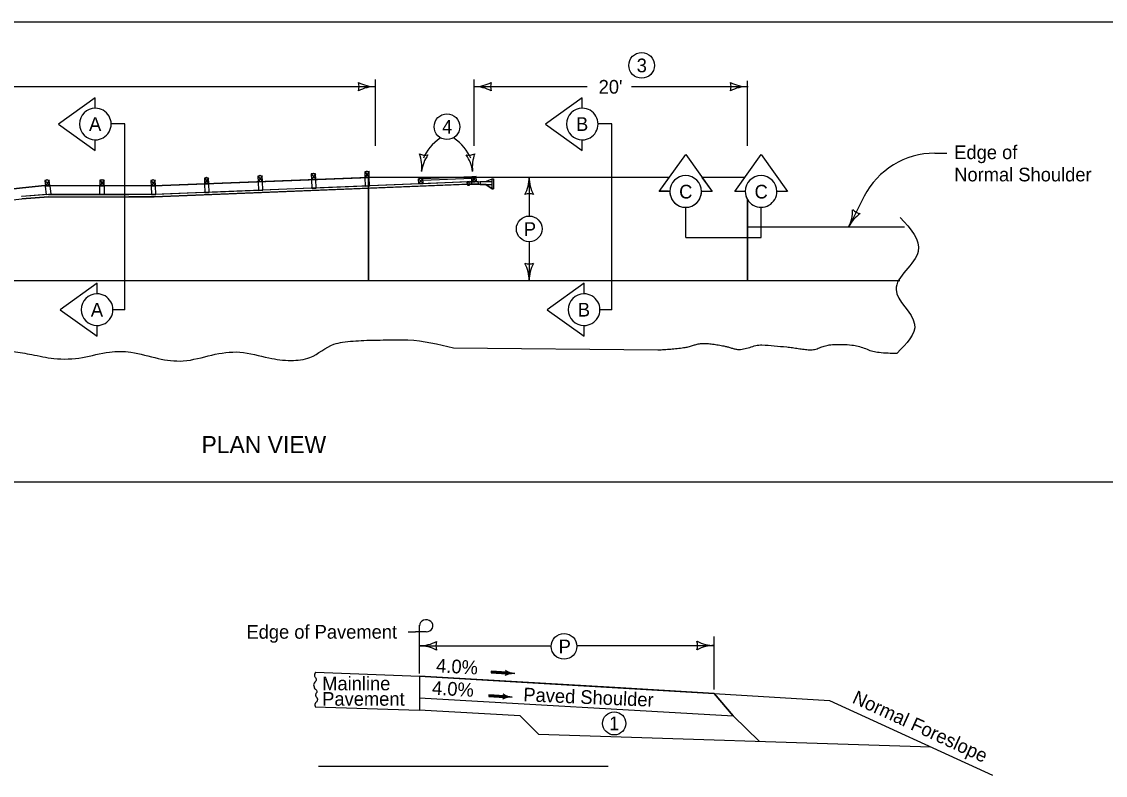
# Model space of a CAD drawing. Extents: x -1548 to 1548, y -960 to 993.
# Drawn here: x -756 to 510, y -231 to 650 of the extents above; entities that cross this region are included whole.
import ezdxf

# ---------------------------------------------------------------- set-up
doc = ezdxf.new("R2010")
doc.units = 0
for name, color, linetype in [('dsnCellElements', 7, 'Continuous'), ('dsnStdBorder', 7, 'Continuous'), ('dsnStdDimension', 7, 'Continuous'), ('dsnStdLabel', 7, 'Continuous'), ('dsnStdLineWork', 7, 'Continuous'), ('dsnStdNote', 7, 'Continuous'), ('dsnStdSection', 7, 'Continuous'), ('dsnStdShading', 7, 'Continuous'), ('Level 4', 7, 'Continuous')]:
    doc.layers.add(name, color=color, linetype=linetype)

msp = doc.modelspace()

# ---------------------------------------------------------------- linework, layer by layer
at = {"layer": 'dsnCellElements'}
for p, q in [((-480.2, 469.6), (-474.9, 463.1)), ((-475.2, 469.8), (-479.9, 462.9)), ((-478.1, 469.7), (-478.2, 469.8)), ((-477.7, 470.7), (-477.7, 470.7)), ((-417.8, 472.1), (-412.5, 465.6)), ((-412.8, 472.3), (-417.5, 465.4)), ((-415.3, 473.2), (-415.3, 473.2)), ((-355.3, 474.6), (-350, 468.1)), ((-350.3, 474.8), (-355, 467.9)), ((-352.8, 475.6), (-352.8, 475.7)), ((-230.2, 468.8), (-287.3, 466.5)), ((-728.9, 464.4), (-723.2, 458.3)), ((-723.9, 464.9), (-728.2, 457.8)), ((-728.2, 457.8), (-723.2, 458.3)), ((-725.7, 458), (-728.2, 457.8)), ((-725.7, 458), (-728.2, 457.8)), ((-727.2, 447.8), (-728.2, 457.8)), ((-726.5, 465.6), (-726.5, 465.7)), ((-723.2, 458.3), (-722.2, 448.3)), ((-664.7, 464.7), (-659.7, 458.1)), ((-659.7, 464.7), (-664.7, 458.1)), ((-664.7, 458.1), (-659.7, 458.1)), ((-664.7, 448.1), (-664.7, 458.1)), ((-662.2, 465.7), (-662.2, 465.8)), ((-659.7, 458.1), (-659.7, 448.1)), ((-605.1, 464.6), (-599.8, 458.1)), ((-600.1, 464.8), (-604.8, 457.9)), ((-602.6, 465.7), (-602.6, 465.7)), ((-222.6, 463.2), (-601.6, 448.1)), ((-222.5, 460.5), (-601.5, 445.3)), ((-601.5, 445.3), (-235.4, 460)), ((-542.7, 467.1), (-537.4, 460.6)), ((-537.7, 467.3), (-542.4, 460.4)), ((-540.2, 468.2), (-540.2, 468.2)), ((-350.2, 458.1), (-354.6, 457.9)), ((-288.4, 460.6), (-292.1, 460.4)), ((-288.4, 460.6), (-292.1, 460.4)), ((-235.4, 460), (-235.6, 462.7)), ((-233, 462.6), (-220.4, 463.2)), ((-220.3, 460), (-232.9, 459.5)), ((-230.1, 459.6), (-230.2, 462.8)), ((-222.5, 460.5), (-222.6, 463.2)), ((-727.2, 447.9), (-756.2, 445.6)), ((-724.8, 448), (-756.1, 445.6)), ((-755.9, 442.9), (-724.6, 445.3)), ((-724.6, 445.3), (-755.9, 442.9)), ((-722.2, 448.3), (-727.2, 447.8)), ((-724.7, 448.1), (-727.2, 447.8)), ((-727.2, 447.8), (-727.2, 447.9)), ((-664.7, 448.1), (-724.7, 448.1)), ((-724.7, 448.1), (-631, 448.1)), ((-724.6, 445.3), (-631, 445.3)), ((-724.6, 445.3), (-631, 445.3)), ((-659.7, 448.1), (-664.7, 448.1)), ((-659.7, 448.1), (-664.7, 448.1)), ((-631, 448.1), (-659.7, 448.1)), ((-604.4, 448.1), (-631, 448.1)), ((-601.6, 448.1), (-631, 448.1)), ((-631, 445.3), (-601.5, 445.3)), ((-601.5, 445.3), (-631, 445.3)), ((-474.5, 453.1), (-479.5, 452.9)), ((-880.3, 430.4), (-755.9, 442.9)), ((-880.3, 430.4), (-755.9, 442.9))]:
    msp.add_line(p, q, dxfattribs=at)
for points in [[(-479.9, 462.9), (-474.9, 463.1), (-475.2, 469.8), (-480.2, 469.6)], [(-417.5, 465.4), (-412.5, 465.6), (-412.8, 472.3), (-417.8, 472.1)], [(-355, 467.9), (-350, 468.1), (-350.3, 474.8), (-355.3, 474.6)], [(-728.2, 457.8), (-723.2, 458.3), (-723.9, 464.9), (-728.9, 464.4)], [(-664.7, 458.1), (-659.7, 458.1), (-659.7, 464.7), (-664.7, 464.7)], [(-604.8, 457.9), (-599.8, 458.1), (-600.1, 464.8), (-605.1, 464.6)], [(-604.4, 447.9), (-599.4, 448.1), (-599.8, 458.1), (-604.8, 457.9)], [(-542.4, 460.4), (-537.4, 460.6), (-537.7, 467.3), (-542.7, 467.1)], [(-542, 450.4), (-537, 450.6), (-537.4, 460.6), (-542.4, 460.4)], [(-479.5, 452.9), (-474.5, 453.1), (-474.9, 463.1), (-479.9, 462.9)], [(-417.1, 455.4), (-412.1, 455.6), (-412.5, 465.6), (-417.5, 465.4)], [(-354.6, 457.9), (-349.6, 458.1), (-350, 468.1), (-355, 467.9)], [(-235.6, 462.7), (-220.4, 463.3), (-214, 463.2), (-206.4, 466.5), (-204.7, 466.5), (-204.9, 454.8), (-206.5, 454.8), (-213.9, 459.8), (-220.3, 459.8), (-232.9, 459.3), (-235.4, 459.2)], [(-233.1, 462.8), (-233.1, 463.1), (-235.6, 463), (-235.6, 462.7), (-235.4, 459.2), (-235.4, 458.9), (-232.9, 459), (-232.9, 459.3)]]:
    msp.add_lwpolyline(points, close=True, dxfattribs=at)
for points in [[(-478, 469.7), (-478.1, 470.1), (-477.4, 470.1), (-477.4, 469.7)], [(-477.9, 470.1), (-477.9, 470.7), (-477.6, 470.7), (-477.5, 470.1)], [(-415.6, 472.2), (-415.6, 472.6), (-414.9, 472.6), (-414.9, 472.2)], [(-415.5, 472.6), (-415.5, 473.1), (-415.1, 473.2), (-415.1, 472.6)], [(-353.1, 474.7), (-353.2, 475.1), (-352.5, 475.1), (-352.5, 474.7)], [(-353, 475.1), (-353, 475.6), (-352.7, 475.7), (-352.6, 475.1)], [(-230.2, 468.8), (-287.3, 466.5)], [(-230.1, 466.6), (-230.2, 468.8)], [(-230, 469), (-225.9, 469.2)], [(-225, 469.1), (-230, 468.9)], [(-230, 468.9), (-225.9, 469)], [(-229.8, 462.9), (-230, 469)], [(-224.7, 463.3), (-230, 468.9)], [(-229.9, 466.6), (-230, 468.8)], [(-229.8, 463.1), (-225, 469.1)], [(-225.9, 469.2), (-225.9, 469)], [(-224.7, 463.3), (-225, 469.1)], [(-726.7, 464.6), (-726.8, 465), (-726.1, 465.1), (-726.1, 464.7)], [(-726.6, 465.1), (-726.7, 465.6), (-726.3, 465.6), (-726.2, 465.1)], [(-662.6, 464.7), (-662.6, 465.2), (-661.9, 465.2), (-661.9, 464.7)], [(-662.4, 465.2), (-662.4, 465.7), (-662, 465.7), (-662, 465.2)], [(-602.9, 464.7), (-603, 465.1), (-602.3, 465.1), (-602.3, 464.7)], [(-602.8, 465.1), (-602.8, 465.7), (-602.5, 465.7), (-602.4, 465.1)], [(-540.5, 467.2), (-540.5, 467.6), (-539.8, 467.6), (-539.8, 467.2)], [(-540.4, 467.6), (-540.4, 468.2), (-540, 468.2), (-540, 467.6)], [(-354.6, 457.9), (-355.2, 457.9), (-412.1, 455.6)], [(-350.2, 458.1), (-355.2, 457.9)], [(-292.1, 460.4), (-349.6, 458.1), (-350.2, 458.1)], [(-287.5, 466.7), (-292.4, 466.5)], [(-287.4, 466.6), (-292.4, 466.4)], [(-292.2, 460.4), (-292.4, 466.5)], [(-287.2, 460.8), (-292.4, 466.4)], [(-292.2, 460.6), (-287.4, 466.6)], [(-287.2, 460.8), (-292.2, 460.6)], [(-287.2, 460.6), (-292.2, 460.4)], [(-235.6, 462.7), (-287.2, 460.6), (-288.4, 460.6)], [(-287.2, 461.2), (-287.4, 466.6)], [(-287.1, 461.2), (-287.3, 466.5)], [(-230.1, 466.8), (-287.2, 464.5)], [(-230.1, 466.7), (-287.2, 464.5)], [(-287.2, 460.8), (-287.2, 461.2)], [(-287, 460.8), (-287.1, 461.2)], [(-232.9, 459.3), (-235.4, 459.2), (-235.6, 462.7), (-233.1, 462.8)], [(-233.1, 462.8), (-220.4, 463.3), (-220.3, 459.8), (-232.9, 459.3)], [(-230, 463.7), (-230.1, 466.6)], [(-230, 463.5), (-230, 463.7)], [(-230, 463.1), (-230, 463.5)], [(-229.8, 463.7), (-229.9, 466.6)], [(-229.8, 463.5), (-229.8, 463.7)], [(-229.8, 463.1), (-229.8, 463.5)], [(-224.7, 463.3), (-229.8, 463.1)], [(-229.8, 463.1), (-225.7, 463.2)], [(-229.8, 462.9), (-225.7, 463.1)], [(-225.9, 463), (-229.4, 462.9)], [(-220.4, 463.3), (-206.4, 463.1)], [(-220.3, 459.8), (-206.5, 459.7)], [(-214, 463.2), (-206.4, 466.5)], [(-213.9, 459.8), (-206.5, 454.8)], [(-206.5, 454.8), (-206.4, 466.5)], [(-206.4, 466.5), (-204.7, 466.5)], [(-204.9, 454.9), (-206.4, 455), (-206.3, 466.4), (-204.7, 466.4)], [(-204.7, 466.5), (-204.9, 454.8)], [(-599.4, 448.1), (-599.4, 448.1), (-601.6, 448.1), (-604.4, 447.9), (-604.4, 448.1)], [(-479.5, 452.9), (-537, 450.6), (-537.7, 450.6), (-542, 450.4), (-542.7, 450.4), (-599.4, 448.1)], [(-537.7, 450.6), (-542.7, 450.4)], [(-417.1, 455.4), (-417.7, 455.4), (-474.5, 453.1)], [(-412.7, 455.6), (-417.7, 455.4)], [(-412.1, 455.6), (-412.7, 455.6), (-417.1, 455.4)], [(-206.5, 454.8), (-204.9, 454.8)]]:
    msp.add_lwpolyline(points, dxfattribs=at)
for centre, radius, start, end in [((-230, 468.8), 0.208, 92.2853, 182.2853), ((-230, 468.8), 0.0517, 92.2853, 182.2853), ((-287.5, 466.5), 0.208, 2.2853, 92.2853), ((-287.2, 460.8), 0.208, 272.2853, 2.2853), ((-229.8, 463.1), 0.208, 182.2853, 272.2853), ((-229.8, 463.1), 0.0517, 182.2853, 272.2853)]:
    msp.add_arc(centre, radius, start, end, dxfattribs=at)
at = {"layer": 'dsnStdBorder'}
msp.add_line((-1547.8, 650), (1547.8, 650), dxfattribs=at)
at = {"layer": 'dsnStdDimension'}
for p, q in [((-1247.4, 574.1), (-342.6, 574.1)), ((-342.6, 504.9), (-342.6, 582.3)), ((-227.5, 504.9), (-227.5, 582.3)), ((-227.5, 574.1), (-95.3, 574.1)), ((-43.7, 574.1), (92.7, 574.1)), ((92, 504.9), (92, 581)), ((-163.1, 468.1), (-163.1, 422.9)), ((-163.1, 392.9), (-163.1, 347.6)), ((53, -130.2), (53, -68.5)), ((-291.3, -79.1), (-137.4, -79.1)), ((-107.5, -78.9), (53, -78.9))]:
    msp.add_line(p, q, dxfattribs=at)
for centre in [(-163.1, 407.9), (-122.4, -79.9)]:
    msp.add_circle(centre, 15, dxfattribs=at)
for centre, radius, start, end in [((-378.2, 574.1), 16.4, 342.2666, 17.7333), ((-342.6, 616.6), 42.5, 241.9275, 270), ((-342.6, 531.6), 42.5, 90, 118.0725), ((-227.5, 616.6), 42.5, 270, 298.0725), ((-227.5, 531.6), 42.5, 61.9275, 90), ((-191.8, 574.1), 16.4, 162.2666, 197.7334), ((56.3, 574.1), 16.4, 342.2666, 17.7333), ((92, 616.6), 42.5, 241.9275, 270), ((92, 531.6), 42.5, 90, 118.0725), ((-205.6, 468.1), 42.5, 331.9275, 0), ((-120.6, 468.1), 42.5, 180, 208.0725), ((-163.1, 432.5), 16.4, 72.2666, 107.7334), ((-163.1, 383.3), 16.4, 252.2666, 287.7333), ((-205.6, 347.6), 42.5, 360, 28.0725), ((-120.6, 347.6), 42.5, 151.9275, 180), ((-291.3, -36.6), 42.5, 270, 298.0725), ((-255.7, -79.1), 16.4, 162.2666, 197.7334), ((17.3, -78.9), 16.4, 342.2666, 17.7333), ((53, -36.4), 42.5, 241.9275, 270), ((-291.3, -121.6), 42.5, 61.9275, 90), ((53, -121.4), 42.5, 90, 118.0725)]:
    msp.add_arc(centre, radius, start, end, dxfattribs=at)
at = {"layer": 'dsnStdLabel'}
for p, q in [((310.7, 496.3), (325, 496.3)), ((228.4, 446), (210.2, 410.3)), ((-304.7, -62.9), (-296, -62.9)), ((-283.5, -62.9), (-296, -62.9)), ((-291.3, -75.7), (-291.3, -54.9)), ((-291.3, -111.7), (-291.3, -75.7)), ((-189.4, -110.9), (-207.6, -109.9)), ((-189.5, -111.8), (-189.5, -111.8)), ((-189.3, -109.9), (-189.3, -109.9)), ((-192.2, -138.5), (-210.4, -137.5)), ((-192.2, -137.5), (-192.2, -137.5)), ((-192.3, -139.5), (-192.3, -139.5))]:
    msp.add_line(p, q, dxfattribs=at)
for points in [[(-189.3, -110), (-207.5, -108.9), (-207.6, -110.8), (-189.5, -111.8), (-189.4, -110.2), (-207.3, -109.1), (-207.3, -110.6), (-189.8, -111.6), (-189.7, -110.5), (-207, -109.4), (-207.1, -110.4), (-190.1, -111.4), (-190, -110.7), (-206.8, -109.6), (-206.9, -110.2), (-190.3, -111.1)], [(-189.7, -108.7), (-189, -109.9), (-189.1, -111.5), (-189.8, -112.9), (-187.1, -112.1), (-183.9, -111.4), (-183, -111.3), (-185.2, -110.7), (-188.4, -109.5), (-189.4, -109), (-189.3, -112.5), (-184.3, -111.3), (-188.9, -109.7), (-188.9, -112.1), (-185.5, -111.2), (-188.5, -110.3), (-188.8, -111.7), (-186.6, -111.2), (-188.2, -110.7), (-188.3, -111.3), (-187.5, -111.2)], [(-192.1, -137.6), (-210.3, -136.5), (-210.4, -138.4), (-192.3, -139.5), (-192.2, -137.9), (-210.1, -136.8), (-210.1, -138.3), (-192.7, -139.2), (-192.5, -138.1), (-209.9, -137), (-209.9, -138), (-192.9, -139), (-192.8, -138.3), (-209.7, -137.2), (-209.7, -137.8), (-193.1, -138.7)], [(-192.5, -136.3), (-191.9, -137.5), (-191.9, -139.2), (-192.6, -140.5), (-189.9, -139.7), (-186.7, -139), (-185.8, -138.9), (-188, -138.4), (-191.3, -137.1), (-192.2, -136.6), (-192.1, -140.1), (-187.1, -138.9), (-191.8, -137.3), (-191.8, -139.7), (-188.4, -138.8), (-191.4, -137.9), (-191.6, -139.3), (-189.4, -138.8), (-191, -138.3), (-191.2, -139), (-190.4, -138.8)]]:
    msp.add_lwpolyline(points, dxfattribs=at)
for centre, radius, start, end in [((310.7, 403.9), 92.4, 90, 152.9341), ((172.3, 429.6), 42.5, 332.9341, 1.0066), ((248, 390.9), 42.5, 124.8616, 152.9341), ((226.4, 442), 16.4, 225.2008, 260.6675)]:
    msp.add_arc(centre, radius, start, end, dxfattribs=at)
for centre, major_axis, start_param, end_param in [((-283.5, -55.8), (-7.81, 0), 1.570796, 6.283185), ((-193.1, -110.7), (3.88, 0), 5.202895, 7.237436), ((-180.8, -131.7), (22.2, 0), 1.537172, 2.061295), ((-178.1, -91.3), (-22.2, 0), 0.954258, 1.478381), ((-195.9, -138.3), (3.88, 0), 5.202895, 7.237436), ((-183.7, -159.3), (22.2, 0), 1.537172, 2.061295), ((-180.9, -118.9), (-22.2, 0), 0.954258, 1.478381)]:
    msp.add_ellipse(centre, major_axis=major_axis, ratio=0.913811, start_param=start_param, end_param=end_param, dxfattribs=at)
at = {"layer": 'dsnStdLineWork'}
for p, q in [((-1096.4, 421.3), (-732.9, 458.1)), ((-602, 458.1), (-732.9, 458.1)), ((-602, 458.1), (-349.9, 468.1)), ((0.6, 468.1), (-350, 468.1)), ((88.7, 468.1), (38.7, 468.1)), ((-0.4, 451.8), (-9.6, 451.9)), ((-0.4, 451.8), (-7, 451.9)), ((92, 442.1), (92, 347.6)), ((226.4, 442.1), (210.2, 410.3)), ((92, 410.3), (275.4, 410.3)), ((-1253.6, 347.6), (270, 347.6)), ((-251.5, 268.9), (-13, 266.5)), ((-412.7, -109.9), (-291.3, -114.8)), ((-291.3, -114.8), (-291.3, -140)), ((-291.3, -114.8), (53, -134.8)), ((52.5, -134.7), (52.5, -134.7)), ((53, -134.8), (75.2, -161.1)), ((53, -134.8), (187.7, -143.1)), ((-413.2, -150.4), (-291.6, -154.4)), ((-291.3, -140), (75.2, -161.1)), ((-291.3, -140), (-291.3, -154.4)), ((187.7, -143.1), (378.3, -230.5)), ((-173.7, -161.2), (-291.5, -154.4)), ((-173.7, -161.2), (-152.3, -182.4)), ((75.2, -161.1), (105.8, -190.9)), ((-152.3, -182.4), (306.1, -197.4)), ((-409.4, -219.7), (-70.9, -219.7))]:
    msp.add_line(p, q, dxfattribs=at)
for points in [[(270.5, 421.3), (291.4, 381.6), (265.5, 337.1), (287.2, 296.7), (266.7, 262.7)], [(-1249.9, 261.8), (-1240.5, 264.4), (-1210.2, 263.8), (-1182.3, 255.8), (-1154.9, 254.7), (-1136.7, 260.4), (-1109.9, 259.8), (-1085.4, 255.3), (-1061.4, 258.7), (-1044.3, 263.8), (-1004.4, 256.4), (-977.6, 252.4), (-953.1, 261.6), (-930.3, 263.3), (-891.5, 257.6), (-892, 257.6), (-870.9, 256), (-833.8, 258.8), (-808.7, 261.7), (-789.9, 265.1), (-766, 264.5), (-744.3, 261.1), (-718.6, 256.5), (-685, 257.7), (-653.6, 263.9), (-628.5, 263.9), (-596.6, 256.5), (-567.5, 253.7), (-533.9, 260.5), (-501.4, 263.9), (-467.2, 257.1), (-441.5, 254.2), (-419.3, 257.7), (-391.3, 273.1), (-381.1, 275.4), (-356.5, 277.6), (-325.9, 278.2), (-304.8, 278.2), (-251.5, 268.9)], [(-13, 266.5), (-11, 266.6), (-3.4, 267.1), (4.1, 267.7), (11.7, 268.5), (19.2, 269.4), (24, 270.4), (28.7, 271.9), (33.3, 273.2), (35.7, 273.7), (38.1, 274), (44.6, 274), (51.2, 273.3), (57.8, 272.3), (64.3, 271.1), (68.3, 270.2), (72.3, 269), (76.2, 267.9), (80.2, 267.1), (83.8, 267.1), (87.3, 267.6), (94.5, 269.5), (101.6, 271.6), (108.8, 272.3), (123.3, 271.3), (137.8, 270), (144.6, 269.2), (151.3, 268.2), (158, 267.2), (164.6, 266.6), (170.4, 267.1), (176.1, 269), (181.7, 271), (187.5, 272.3), (194.9, 272.8), (202.6, 272.9), (213.9, 272.2), (217.7, 271.7), (224.7, 269.9), (231.6, 267.3), (238.5, 264.9), (245.6, 263.7), (266.7, 262.7)], [(-412.7, -109.9), (-413.9, -114.5), (-412.9, -116.1), (-412, -118.3), (-412.6, -120.4), (-414.5, -122.8), (-415, -124.7), (-414.5, -127), (-413.6, -129.4), (-412.6, -130.1), (-411.2, -132.6), (-411.2, -133.4)], [(-411.2, -133.4), (-411.4, -133.7), (-411.6, -133.9), (-412, -134.5), (-412.5, -135.7), (-412.7, -137), (-412.6, -137.5), (-412.6, -137.8), (-412.5, -138.1), (-412.3, -138.5), (-412, -138.8), (-411.7, -139.2), (-411.4, -139.6), (-411.3, -139.9), (-411.2, -140.2), (-410.9, -140.7), (-410.6, -141.9), (-410.6, -142), (-410.6, -142.1), (-410.7, -142.9), (-410.9, -143.4), (-411.2, -144), (-411.6, -144.6), (-412.1, -145.1), (-412.7, -145.7), (-412.9, -146), (-413.1, -146.3), (-413.3, -146.8), (-413.5, -147.3), (-413.6, -147.7), (-413.6, -148), (-413.6, -148.2), (-413.5, -148.8), (-413.4, -149.3), (-413.3, -149.8), (-413.1, -150.4)]]:
    msp.add_spline(points, degree=3, dxfattribs=at)
at = {"layer": 'dsnStdNote'}
for centre, radius in [((-31.8, 598.9), 15), ((-259.2, 527.3), 15), ((-63.8, -169.8), 13.5)]:
    msp.add_circle(centre, radius, dxfattribs=at)
for centre, radius, start, end in [((-284.5, 510.5), 16.4, 245.1764, 280.6431), ((-331.1, 480.4), 42.5, 352.9098, 20.9823), ((-246.7, 469.9), 42.5, 144.8373, 172.9098), ((-233.7, 510.5), 16.4, 259.3569, 294.8236), ((-271.5, 469.9), 42.5, 7.0902, 35.1627), ((-187.1, 480.4), 42.5, 159.0177, 187.0902)]:
    msp.add_arc(centre, radius, start, end, dxfattribs=at)
for centre, major_axis, start_param, end_param in [((-199.7, 487.5), (-89.1, -12.3), 5.48501, 5.97728), ((-318.5, 487.5), (89.1, -12.3), 0.305948, 0.800412)]:
    msp.add_ellipse(centre, major_axis=major_axis, ratio=0.555556, start_param=start_param, end_param=end_param, dxfattribs=at)
at = {"layer": 'dsnStdSection'}
for p, q in [((-635.6, 530.7), (-651.3, 530.7)), ((-635.6, 313.5), (-635.6, 530.7)), ((-66.5, 530.7), (-82.3, 530.7)), ((-66.5, 313.5), (-66.5, 530.7)), ((19.7, 397.7), (19.7, 433.2)), ((107.8, 397.7), (107.8, 433.2)), ((19.7, 397.7), (107.8, 397.7)), ((-635.6, 313.5), (-649.5, 313.5)), ((-66.5, 313.5), (-80.5, 313.5))]:
    msp.add_line(p, q, dxfattribs=at)
for points in [[(-670.1, 548.9), (-670.1, 561.2), (-713.2, 530.4), (-670.1, 499.6), (-670.1, 511.9)], [(-101.1, 548.9), (-101.1, 561.2), (-144.2, 530.4), (-101.1, 499.6), (-101.1, 511.9)], [(1.2, 451.6), (-11.1, 451.6), (19.7, 494.8), (50.5, 451.6), (38.2, 451.6)], [(89.3, 451.6), (77, 451.6), (107.8, 494.8), (138.6, 451.6), (126.3, 451.6)], [(-668, 331.9), (-668, 344.3), (-711.1, 313.5), (-668, 282.6), (-668, 295)], [(-99, 331.9), (-99, 344.3), (-142.1, 313.5), (-99, 282.6), (-99, 295)]]:
    msp.add_lwpolyline(points, dxfattribs=at)
for centre, start, end in [((-670.1, 530.4), 90.0008, 269.9992), ((-670.1, 530.4), 269.9992, 90.0008), ((-101.1, 530.4), 90.0008, 269.9992), ((-101.1, 530.4), 269.9992, 90.0008), ((19.7, 451.6), 0.0008, 179.9992), ((107.8, 451.6), 0.0008, 179.9992), ((19.7, 451.6), 179.9992, 0.0008), ((107.8, 451.6), 179.9992, 0.0008), ((-668, 313.5), 90.0008, 269.9992), ((-668, 313.5), 269.9992, 90.0008), ((-99, 313.5), 90.0008, 269.9992), ((-99, 313.5), 269.9992, 90.0008)]:
    msp.add_arc(centre, 18.5, start, end, dxfattribs=at)
at = {"layer": 'dsnStdShading'}
msp.add_lwpolyline([(-62.9, -128.1), (-62.9, -128.1), (-291.3, -114.8), (-291.3, -140), (75.2, -161.1), (53, -134.8), (-62.9, -128.1)], dxfattribs=at)
at = {"layer": 'Level 4'}
for p, q in [((-732.9, 458.1), (-1096.4, 421.3)), ((-602, 458.1), (-732.9, 458.1)), ((-351, 468.1), (-602, 458.1)), ((-351, 347.6), (-351, 468.1)), ((0.6, 468.1), (-351, 468.1)), ((-351, 468.1), (-351, 347.6)), ((-11.1, 451.6), (0.6, 468.1)), ((88.7, 468.1), (38.7, 468.1)), ((38.7, 468.1), (50.5, 451.6)), ((77, 451.6), (88.7, 468.1)), ((1.2, 451.6), (-11.1, 451.6)), ((50.5, 451.6), (38.2, 451.6)), ((89.3, 451.6), (77, 451.6)), ((92, 347.6), (92, 442.1)), ((-1253.7, 347.6), (-351, 347.6)), ((-351, 347.6), (92, 347.6)), ((607.7, 112), (-1547.8, 112))]:
    msp.add_line(p, q, dxfattribs=at)
msp.add_circle((-163.1, 407.9), 15, dxfattribs=at)
for centre, end in [((19.7, 451.6), 0), ((107.8, 451.6), 211.0798)]:
    msp.add_arc(centre, 18.5, 180, end, dxfattribs=at)

# ---------------------------------------------------------------- texts
at = {"layer": 'dsnStdDimension'}
for s, p in [("20'", (-82, 565.9)), ('P', (-169.4, 399.7)), ('P', (-128.7, -88))]:
    msp.add_text(s, height=16, dxfattribs=at).set_placement(p)
at = {"layer": 'dsnStdLabel'}
for s, height, p in [('Edge of ', 16, (333.5, 489.4)), ('Normal Shoulder', 16, (333.5, 463.4)), ('PLAN VIEW', 20, (-546, 145.9)), ('Edge of Pavement', 16, (-493.5, -70.9)), ('Mainline', 16, (-405, -131.2)), ('Pavement', 16, (-405, -149.2))]:
    msp.add_text(s, height=height, dxfattribs=at).set_placement(p)
for s, rotation, p in [('4.0%', 356.6992, (-272.2, -110)), ('4.0%', 356.6992, (-277, -136.1)), ('Paved Shoulder ', 357.5923, (-170.2, -144)), ('Normal Foreslope', 335.372, (213.2, -145.3))]:
    msp.add_text(s, height=16, rotation=rotation, dxfattribs=at).set_placement(p)
at = {"layer": 'dsnStdNote'}
for s, p in [('3', (-37.5, 590.9)), ('4', (-264.9, 519.3)), ('1', (-69.7, -177.8))]:
    msp.add_text(s, height=16, dxfattribs=at).set_placement(p)
at = {"layer": 'dsnStdSection'}
for s, p in [('A', (-677.4, 522.4)), ('B', (-108.4, 522.4)), ('A', (-675.3, 305.5)), ('B', (-106.3, 305.5))]:
    msp.add_text(s, height=16, dxfattribs=at).set_placement(p)
for p in [(12.1, 443.4), (100.2, 443.4)]:
    msp.add_text('C', height=16, rotation=360, dxfattribs=at).set_placement(p)

doc.saveas('drawing.dxf')
